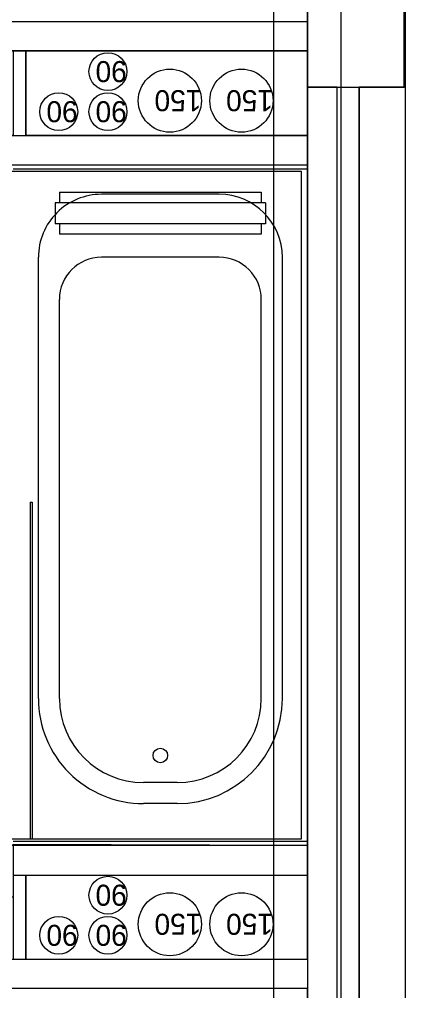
# Model space of a CAD drawing. Extents: x 1278 to 1356, y -253.7 to -224.
# Drawn here: x 1310.704 to 1311.622, y -239.071 to -236.76 of the extents above; entities that cross this region are included whole.
import ezdxf

# ---------------------------------------------------------------- set-up
doc = ezdxf.new("R2010")
doc.units = 0
for name, color, linetype in [('Level 1', 7, 'Continuous'), ('Level 11', 7, 'Continuous'), ('Level 36', 7, 'Continuous'), ('Level 41', 7, 'Continuous'), ('Level 65', 7, 'Continuous'), ('Level 66', 7, 'Continuous'), ('Level 67', 7, 'Continuous'), ('Level 70', 7, 'Continuous'), ('Level 93', 7, 'Continuous')]:
    doc.layers.add(name, color=color, linetype=linetype)

msp = doc.modelspace()

# ---------------------------------------------------------------- linework, layer by layer
at = {"layer": 'Level 1'}
for p, q in [((1309.9127, -236.8352), (1311.389, -236.8352)), ((1311.389, -238.7263), (1309.8427, -238.7263)), ((1311.389, -239.0663), (1309.0619, -239.0663))]:
    msp.add_line(p, q, dxfattribs=at)
at = {"layer": 'Level 11'}
for p, q in [((1311.389, -237.1163), (1310.689, -237.1163)), ((1311.389, -238.7163), (1311.389, -237.1163)), ((1311.179, -237.1763), (1310.899, -237.1763)), ((1310.749, -238.3763), (1310.749, -237.3263)), ((1311.179, -237.3263), (1310.899, -237.3263)), ((1311.329, -238.3763), (1311.329, -237.3263)), ((1310.799, -238.3763), (1310.799, -237.4263)), ((1311.279, -238.3763), (1311.279, -237.4263)), ((1311.079, -238.5763), (1310.999, -238.5763)), ((1311.079, -238.6263), (1310.999, -238.6263)), ((1311.389, -238.7163), (1310.689, -238.7163))]:
    msp.add_line(p, q, dxfattribs=at)
msp.add_circle((1311.039, -238.5118), 0.0173, dxfattribs=at)
for centre, radius, start, end in [((1310.899, -237.3263), 0.15, 89.9999, 180.0002), ((1311.179, -237.3263), 0.15, 360, 90), ((1310.899, -237.4263), 0.1, 90.0001, 179.9999), ((1311.179, -237.4263), 0.1, 360, 90.0001), ((1310.999, -238.3763), 0.25, 180, 270.0001), ((1310.999, -238.3763), 0.2, 180, 270), ((1311.079, -238.3763), 0.25, 269.9999, 359.9999), ((1311.079, -238.3763), 0.2, 270, 0)]:
    msp.add_arc(centre, radius, start, end, dxfattribs=at)
at = {"layer": 'Level 36'}
for p, q in [((1310.7294, -237.909), (1310.7294, -238.709)), ((1310.7294, -237.909), (1310.7344, -237.909)), ((1310.7294, -237.909), (1310.7294, -238.709)), ((1310.7294, -237.909), (1310.7344, -237.909)), ((1310.7294, -237.909), (1310.7294, -238.709)), ((1310.7294, -237.909), (1310.7344, -237.909)), ((1310.7344, -237.909), (1310.7344, -238.709)), ((1310.7344, -237.909), (1310.7344, -238.709)), ((1310.7344, -237.909), (1310.7344, -238.709))]:
    msp.add_line(p, q, dxfattribs=at)
at = {"layer": 'Level 41'}
for centre, radius in [((1310.9143, -236.8843), 0.045), ((1311.0616, -236.9535), 0.075), ((1311.2318, -236.9535), 0.075), ((1310.7975, -236.9797), 0.045), ((1310.9143, -236.9797), 0.045), ((1310.9143, -238.8443), 0.045), ((1311.0616, -238.9135), 0.075), ((1311.2318, -238.9135), 0.075), ((1310.7975, -238.9397), 0.045), ((1310.9143, -238.9397), 0.045)]:
    msp.add_circle(centre, radius, dxfattribs=at)
at = {"layer": 'Level 65'}
for p, q in [((1309.8277, -237.1213), (1311.374, -237.1213)), ((1311.374, -237.1213), (1311.374, -238.7113)), ((1311.374, -238.7113), (1309.8277, -238.7113))]:
    msp.add_line(p, q, dxfattribs=at)
at = {"layer": 'Level 66'}
for p, q in [((1311.389, -237.0363), (1311.389, -231.934)), ((1311.6219, -243.584), (1311.6219, -232.264)), ((1311.6219, -243.584), (1311.6219, -232.264)), ((1311.6219, -243.584), (1311.6219, -232.264)), ((1311.6219, -243.584), (1311.6219, -232.264)), ((1311.6219, -243.584), (1311.6219, -232.264)), ((1309.0619, -236.7652), (1311.3902, -236.7652)), ((1310.0177, -236.7652), (1311.3902, -236.7652)), ((1310.719, -236.8352), (1310.719, -237.0363)), ((1311.459, -242.8713), (1311.459, -236.9213)), ((1311.5119, -242.8713), (1311.5119, -236.9213)), ((1309.9127, -237.0363), (1311.389, -237.0363)), ((1309.8427, -237.1063), (1311.389, -237.1063)), ((1311.389, -238.7263), (1311.389, -237.1063)), ((1310.799, -237.1713), (1311.279, -237.1713)), ((1310.799, -237.1713), (1310.799, -237.1963)), ((1311.279, -237.1713), (1311.279, -237.1963)), ((1311.289, -237.1963), (1310.789, -237.1963)), ((1310.789, -237.1963), (1310.789, -237.2463)), ((1311.289, -237.1963), (1311.289, -237.2463)), ((1311.289, -237.2463), (1310.789, -237.2463)), ((1310.799, -237.2463), (1310.799, -237.2713)), ((1311.279, -237.2463), (1311.279, -237.2713)), ((1311.279, -237.2713), (1310.799, -237.2713)), ((1310.689, -238.7963), (1311.389, -238.7963)), ((1310.719, -238.7963), (1310.719, -238.9963)), ((1311.389, -238.9963), (1311.389, -238.7963)), ((1309.9127, -238.9963), (1311.389, -238.9963)), ((1311.389, -242.8713), (1311.389, -239.0663))]:
    msp.add_line(p, q, dxfattribs=at)
msp.add_lwpolyline([(1311.389, -236.9213), (1311.619, -236.9213), (1311.619, -236.2213), (1311.389, -236.2213)], close=True, dxfattribs=at)
at = {"layer": 'Level 67'}
for points in [[(1311.389, -236.8352), (1309.1319, -236.8352), (1309.1319, -237.1748), (1309.0619, -237.1748), (1309.0619, -236.7652), (1311.389, -236.7652)], [(1309.8427, -236.8352), (1309.8427, -237.1063), (1311.389, -237.1063), (1311.389, -237.0363), (1310.719, -237.0363), (1310.719, -236.8352), (1310.689, -236.8352), (1310.689, -237.0363), (1309.9127, -237.0363), (1309.9127, -236.8352)], [(1311.389, -242.8713), (1311.459, -242.8713), (1311.459, -236.9213), (1311.389, -236.9213)], [(1311.5119, -242.8713), (1311.6219, -242.8713), (1311.6219, -236.9213), (1311.5119, -236.9213)], [(1311.389, -238.9963), (1311.389, -239.0663), (1309.0619, -239.0663), (1309.0619, -237.9048), (1309.1319, -237.9048), (1309.1319, -238.9963), (1309.8427, -238.9963), (1309.8427, -238.7263), (1310.689, -238.7236), (1310.689, -238.8486), (1309.9127, -238.8486), (1309.9127, -238.9963)], [(1311.389, -238.7963), (1311.389, -238.7263), (1310.689, -238.7236), (1310.689, -238.9963), (1310.719, -238.9963), (1310.719, -238.7963)]]:
    msp.add_lwpolyline(points, close=True, dxfattribs=at)
at = {"layer": 'Level 70'}
msp.add_line((1311.469, -250.7923), (1311.469, -229.6198), dxfattribs=at)
at = {"layer": 'Level 93'}
msp.add_line((1311.309, -246.757), (1311.309, -236.1407), dxfattribs=at)

# ---------------------------------------------------------------- texts
at = {"layer": 'Level 41'}
for s, p in [('90', (1310.9593, -236.8593)), ('150', (1311.1366, -236.9285)), ('150', (1311.3068, -236.9285)), ('90', (1310.8425, -236.9547)), ('90', (1310.9593, -236.9547)), ('90', (1310.9593, -238.8193)), ('150', (1311.1366, -238.8885)), ('150', (1311.3068, -238.8885)), ('90', (1310.8425, -238.9147)), ('90', (1310.9593, -238.9147))]:
    msp.add_text(s, height=0.05, rotation=180, dxfattribs=at).set_placement(p)

doc.saveas('drawing.dxf')
